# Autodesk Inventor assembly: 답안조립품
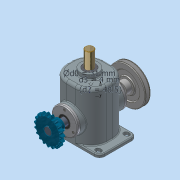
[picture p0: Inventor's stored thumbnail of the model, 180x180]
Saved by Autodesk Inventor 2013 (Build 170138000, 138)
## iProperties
Created: 2014-12
Part Number: 답안조립품
Document SubType Name: Assembly
Designer: WINDOWS7
Author: WINDOWS7
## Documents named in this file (15)
- C:\Users\WINDOWS7\Desktop\새 폴더\답안조립품.iam
- C:\Users\WINDOWS7\Desktop\새 폴더\본체.ipt
- C:\Users\WINDOWS7\Desktop\새 폴더\커버.ipt
- C:\Users\WINDOWS7\Desktop\새 폴더\부시.ipt
- C:\Users\WINDOWS7\Desktop\새 폴더\베어링 6205.ipt
- C:\Users\WINDOWS7\Desktop\새 폴더\편심축.ipt
- C:\Users\WINDOWS7\Desktop\새 폴더\멈춤링.ipt
- C:\Users\WINDOWS7\Desktop\새 폴더\오일실.ipt
- C:\Users\WINDOWS7\Desktop\새 폴더\M4x0.5.ipt
- C:\Users\WINDOWS7\Desktop\새 폴더\키 8x8.ipt
- C:\Users\WINDOWS7\Desktop\새 폴더\체인 스프로킷.ipt
- C:\Users\WINDOWS7\Desktop\새 폴더\멈춤나사 M5x0.5.ipt
- C:\Users\WINDOWS7\Desktop\새 폴더\V-벨트풀리.ipt
- C:\Users\WINDOWS7\Desktop\새 폴더\슬라이드.ipt
- C:\Users\WINDOWS7\Desktop\새 폴더\7-가변스프링.ipt
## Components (9 placed, 4 different names)
1. M4x0.5:1
2. M4x0.5:2
3. M4x0.5:3
4. M4x0.5:4
5. M4x0.5:5
6. M4x0.5:6
7. 5-체인 스프로킷:1 — 각도:3
8. V-벨트풀리:1 — 각도:4
9. 7-가변스프링:1
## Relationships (2: Angle 2)
- 각도:3 [Angle]: 5-체인 스프로킷:1
- 각도:4 [Angle]: V-벨트풀리:1
